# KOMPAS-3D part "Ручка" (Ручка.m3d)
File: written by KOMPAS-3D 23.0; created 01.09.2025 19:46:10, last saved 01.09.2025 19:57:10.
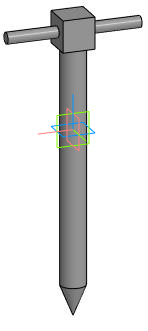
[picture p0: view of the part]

Document properties: Автор: Inspektor_Kot; Полное имя файла: I:\Autodesk Inventor Projects\ИМ-ИТ ЦД\Вариант 3\Ручка.m3d

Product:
- Part/product: Ручка
    Масса: 0.499335

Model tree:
1. Эскиз:1  (with: Элемент вращения:1)
2. Элемент вращения:1
     Угол 1 = 360
3. Эскиз:3  (with: Элемент вращения:1)
4. Элемент выдавливания:1
     Расстояние 1 = 50
5. Эскиз:5  (with: Элемент выдавливания:1)
6. Элемент выдавливания:2
     Расстояние 1 = 80
7. Эскиз:6  (with: Элемент выдавливания:1, Элемент выдавливания:2)
8. Элемент выдавливания:3
     Расстояние 1 = 80

Expressions: 20 + 30
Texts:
  Угловой размер с обрывом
